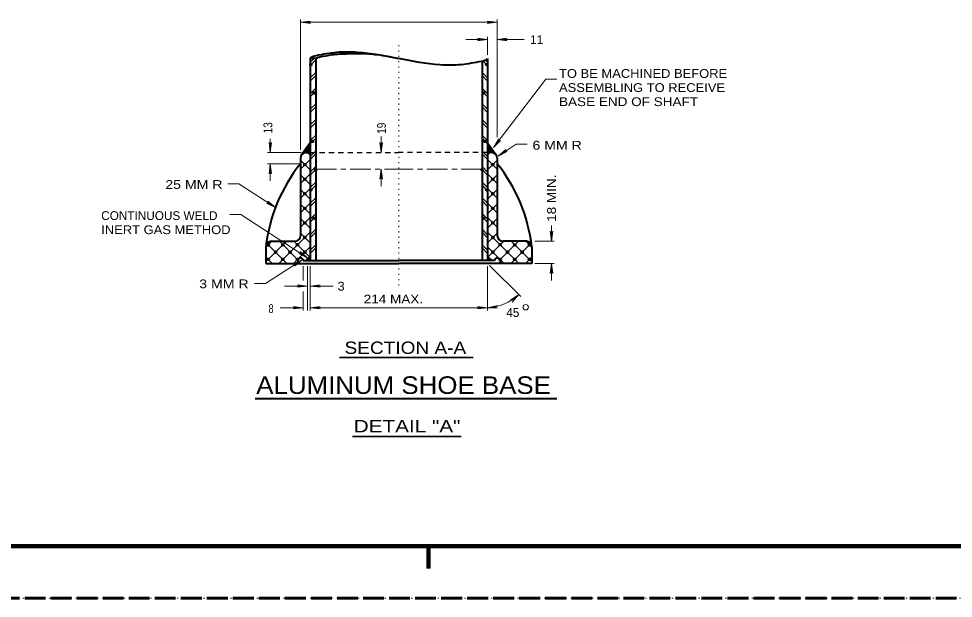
# Model space of a CAD drawing. Extents: x 312583 to 312854, y 144419 to 144597.
# Drawn here: x 312691.9 to 312772.7, y 144418.6 to 144468.7 of the extents above; entities that cross this region are included whole.
import ezdxf
from ezdxf.enums import TextEntityAlignment as Align

# ---------------------------------------------------------------- set-up
doc = ezdxf.new("R2010")
doc.units = 0
doc.header["$LTSCALE"] = 0.3
doc.header["$PDMODE"] = 32
doc.header["$PDSIZE"] = 0.15
for name, pattern in [('DOTTED', [1.5, 0.3, -1.2]), ('LONG_DASH_SHORT_DASH', [9.9, 6, -1.2, 1.5, -1.2]), ('LONG_DASHED', [7.5, 6, -1.5]), ('SHORT_DASHED', [2.7, 1.5, -1.2])]:
    doc.linetypes.add(name, pattern=pattern)
for name, color, linetype, lineweight in [('1', 7, 'Continuous', 40), ('2', 7, 'Continuous', 13), ('62', 7, 'DOTTED', 13), ('63', 7, 'LONG_DASHED', 60)]:
    doc.layers.add(name, color=color, linetype=linetype, lineweight=lineweight)

msp = doc.modelspace()

# ---------------------------------------------------------------- linework, layer by layer
at = {"layer": '1'}
for p, q in [((312717.1224, 144465.2785), (312717.1224, 144447.7909)), ((312717.6054, 144465.2785), (312717.1224, 144465.2785)), ((312717.6054, 144465.2785), (312717.6054, 144447.7909)), ((312732.4557, 144465.2785), (312732.4557, 144447.7909)), ((312731.9804, 144465.0332), (312731.9804, 144447.7909)), ((312717.1224, 144457.9722), (312716.3787, 144456.9372)), ((312732.4557, 144457.9722), (312733.2071, 144456.9372)), ((312716.2867, 144456.6535), (312716.2867, 144449.9452)), ((312716.7697, 144457.1365), (312717.1301, 144457.1365)), ((312732.8161, 144457.1365), (312732.4557, 144457.1365)), ((312733.2991, 144456.6535), (312733.2991, 144449.9452)), ((312713.7721, 144449.4699), (312715.8114, 144449.4699)), ((312735.8137, 144449.4699), (312733.7744, 144449.4699)), ((312713.2891, 144448.9869), (312713.2891, 144447.5532)), ((312736.2891, 144448.9869), (312736.2891, 144447.5532)), ((312713.2891, 144447.5532), (312724.7891, 144447.5532)), ((312716.0491, 144447.7909), (312716.0491, 144447.5532)), ((312716.5244, 144447.7909), (312724.7891, 144447.7909)), ((312716.7544, 144447.7909), (312717.1224, 144448.1589)), ((312733.0537, 144447.7909), (312724.7891, 144447.7909)), ((312736.2891, 144447.5532), (312724.7891, 144447.5532)), ((312732.8314, 144447.7909), (312732.4557, 144448.1589)), ((312733.5367, 144447.7909), (312733.5367, 144447.5532))]:
    msp.add_line(p, q, dxfattribs=at)
at = {"layer": '1', "lineweight": 13}
for p, q in [((312717.1224, 144464.9489), (312717.4597, 144465.2785)), ((312717.1224, 144464.6805), (312717.6054, 144465.1559)), ((312732.4557, 144464.6805), (312732.0877, 144465.0485)), ((312732.4557, 144464.9489), (312732.2564, 144465.1482)), ((312717.1224, 144463.5919), (312717.6054, 144464.0749)), ((312717.1224, 144463.3235), (312717.6054, 144463.7989)), ((312732.4557, 144463.5919), (312731.9804, 144464.0749)), ((312732.4557, 144463.3235), (312731.9804, 144463.7989)), ((312717.1224, 144462.2349), (312717.6054, 144462.7179)), ((312717.1224, 144461.9665), (312717.6054, 144462.4495)), ((312732.4557, 144462.2349), (312731.9804, 144462.7179)), ((312732.4557, 144461.9665), (312731.9804, 144462.4495)), ((312717.1224, 144460.8855), (312717.6054, 144461.3609)), ((312732.4557, 144460.8855), (312731.9804, 144461.3609)), ((312717.1224, 144460.6095), (312717.6054, 144461.0925)), ((312732.4557, 144460.6095), (312731.9804, 144461.0925)), ((312717.1224, 144459.5285), (312717.6054, 144460.0039)), ((312717.1224, 144459.2525), (312717.6054, 144459.7355)), ((312732.4557, 144459.5285), (312731.9804, 144460.0039)), ((312732.4557, 144459.2525), (312731.9804, 144459.7355)), ((312717.1224, 144458.1715), (312717.6054, 144458.6545)), ((312717.1224, 144457.8955), (312717.6054, 144458.3785)), ((312732.4557, 144458.1715), (312731.9804, 144458.6545)), ((312732.4634, 144457.8955), (312731.9804, 144458.3785)), ((312717.1224, 144456.8145), (312717.6054, 144457.2975)), ((312732.4557, 144456.8145), (312731.9804, 144457.2975)), ((312716.2867, 144455.7182), (312717.1301, 144456.5539)), ((312717.1301, 144455.6415), (312716.2867, 144456.4849)), ((312717.1301, 144456.9065), (312716.9001, 144457.1365)), ((312717.1224, 144456.5462), (312717.6054, 144457.0215)), ((312732.4557, 144456.5462), (312731.9804, 144457.0215)), ((312732.4557, 144456.9065), (312732.6857, 144457.1365)), ((312733.2991, 144455.7182), (312732.4557, 144456.5539)), ((312732.4557, 144455.6415), (312733.2991, 144456.4849)), ((312717.1224, 144455.4575), (312717.6054, 144455.9405)), ((312717.1224, 144455.1892), (312717.6054, 144455.6722)), ((312732.4557, 144455.4575), (312731.9804, 144455.9405)), ((312732.4557, 144455.1892), (312731.9804, 144455.6722)), ((312716.2867, 144454.4609), (312717.1301, 144455.2965)), ((312717.1301, 144454.3765), (312716.2867, 144455.2199)), ((312733.2991, 144454.4609), (312732.4557, 144455.2965)), ((312732.4557, 144454.3765), (312733.2991, 144455.2199)), ((312716.2867, 144453.1959), (312717.1301, 144454.0392)), ((312717.1224, 144454.1082), (312717.6054, 144454.5835)), ((312717.1224, 144453.8322), (312717.6054, 144454.3152)), ((312732.4557, 144454.1082), (312731.9804, 144454.5835)), ((312732.4557, 144453.8322), (312731.9804, 144454.3152)), ((312733.2991, 144453.1959), (312732.4557, 144454.0392)), ((312717.1301, 144453.1192), (312716.2867, 144453.9549)), ((312717.1301, 144452.7512), (312717.6054, 144453.2265)), ((312732.4557, 144452.7512), (312731.9804, 144453.2265)), ((312732.4557, 144453.1192), (312733.2991, 144453.9549)), ((312716.2867, 144451.9385), (312717.1301, 144452.7742)), ((312717.1224, 144451.8542), (312716.2867, 144452.6899)), ((312717.1224, 144452.4829), (312717.6054, 144452.9582)), ((312732.4557, 144452.4829), (312731.9804, 144452.9582)), ((312733.2991, 144451.9385), (312732.4557, 144452.7742)), ((312732.4557, 144451.8542), (312733.2991, 144452.6899)), ((312717.1224, 144451.3942), (312717.6054, 144451.8772)), ((312717.1224, 144451.1259), (312717.6054, 144451.6012)), ((312732.4557, 144451.3942), (312731.9804, 144451.8772)), ((312732.4557, 144451.1259), (312731.9804, 144451.6012)), ((312716.2867, 144450.6735), (312717.1224, 144451.5169)), ((312717.1224, 144450.5892), (312716.2867, 144451.4325)), ((312733.2991, 144450.6735), (312732.4557, 144451.5169)), ((312732.4557, 144450.5892), (312733.2991, 144451.4325)), ((312714.4237, 144447.5532), (312717.1301, 144450.2519)), ((312717.1224, 144449.3319), (312716.2867, 144450.1675)), ((312717.1224, 144450.0372), (312717.6054, 144450.5202)), ((312717.1224, 144449.7689), (312717.6054, 144450.2519)), ((312732.4557, 144450.0372), (312731.9804, 144450.5202)), ((312732.4557, 144449.7689), (312731.9804, 144450.2519)), ((312735.1621, 144447.5532), (312732.4557, 144450.2519)), ((312732.4557, 144449.3319), (312733.2991, 144450.1675)), ((312713.2891, 144447.6835), (312715.0754, 144449.4699)), ((312713.2891, 144448.9409), (312713.8181, 144449.4699)), ((312715.1137, 144447.5532), (312713.2891, 144449.3702)), ((312716.0644, 144447.8675), (312714.4621, 144449.4699)), ((312717.1224, 144448.0669), (312715.7271, 144449.4699)), ((312717.1224, 144448.6879), (312717.6054, 144449.1632)), ((312732.4557, 144448.6879), (312731.9804, 144449.1632)), ((312732.4557, 144448.0669), (312733.8587, 144449.4699)), ((312733.5214, 144447.8675), (312735.1237, 144449.4699)), ((312734.4721, 144447.5532), (312736.2891, 144449.3702)), ((312736.2891, 144447.6835), (312734.5027, 144449.4699)), ((312736.2891, 144448.9409), (312735.7677, 144449.4699)), ((312715.6811, 144447.5532), (312717.1301, 144448.9945)), ((312717.1224, 144448.4119), (312717.6054, 144448.8949)), ((312732.4557, 144448.4119), (312731.9804, 144448.8949)), ((312733.8971, 144447.5532), (312732.4557, 144448.9945)), ((312713.8487, 144447.5532), (312713.2891, 144448.1129)), ((312717.5901, 144447.7909), (312717.6054, 144447.8062)), ((312731.9957, 144447.7909), (312731.9804, 144447.8062)), ((312735.7371, 144447.5532), (312736.2891, 144448.1129))]:
    msp.add_line(p, q, dxfattribs=at)
at = {"layer": '1', "lineweight": 25}
for p, q in [((312716.5014, 144457.1135), (312717.1224, 144457.7345)), ((312716.6087, 144457.1212), (312717.1224, 144457.6349)), ((312716.7084, 144457.1289), (312717.1224, 144457.5429)), ((312716.7467, 144457.4509), (312717.1224, 144457.8265)), ((312716.8157, 144457.1365), (312717.1224, 144457.4509)), ((312716.9077, 144457.1365), (312717.1224, 144457.3512)), ((312716.9921, 144457.7882), (312717.1224, 144457.9262)), ((312716.9997, 144457.1365), (312717.1224, 144457.2592)), ((312732.5937, 144457.7882), (312732.4557, 144457.9262)), ((312732.8314, 144457.4509), (312732.4557, 144457.8265)), ((312733.0767, 144457.1135), (312732.4557, 144457.7345)), ((312732.9771, 144457.1212), (312732.4557, 144457.6349)), ((312732.8697, 144457.1289), (312732.4557, 144457.5429)), ((312732.7701, 144457.1365), (312732.4557, 144457.4509)), ((312732.6781, 144457.1365), (312732.4557, 144457.3512)), ((312732.5784, 144457.1365), (312732.4557, 144457.2592)), ((312717.0994, 144457.1365), (312717.1224, 144457.1672)), ((312732.4864, 144457.1365), (312732.4557, 144457.1672)), ((312716.8387, 144447.7909), (312717.1224, 144448.0822)), ((312716.9307, 144447.7909), (312717.1224, 144447.9825)), ((312717.0304, 144447.7909), (312717.1224, 144447.8905)), ((312717.1224, 144447.7909), (312717.1224, 144447.7985)), ((312732.7471, 144447.7909), (312732.4557, 144448.0822)), ((312732.6551, 144447.7909), (312732.4557, 144447.9825)), ((312732.5554, 144447.7909), (312732.4557, 144447.8905)), ((312732.4634, 144447.7909), (312732.4557, 144447.7985))]:
    msp.add_line(p, q, dxfattribs=at)
at = {"layer": '1', "linetype": 'SHORT_DASHED', "lineweight": 25}
for p in [(312717.1301, 144457.1365), (312732.4557, 144457.1365)]:
    msp.add_line(p, (312724.7891, 144457.1365), dxfattribs=at)
at = {"layer": '1', "linetype": 'LONG_DASH_SHORT_DASH', "lineweight": 13}
for p in [(312717.6054, 144455.6952), (312731.9804, 144455.6952)]:
    msp.add_line(p, (312724.7891, 144455.6952), dxfattribs=at)
at = {"layer": '1', "lineweight": 158}
for p, q in [((312616.5, 144423.0846), (312849, 144423.0846)), ((312727.35, 144421.1646), (312727.35, 144423.0846))]:
    msp.add_line(p, q, dxfattribs=at)
at = {"layer": '1'}
for centre, radius, start, end in [((312716.7659, 144456.6555), 0.4792, 90, 180), ((312732.8161, 144456.6555), 0.4792, 0, 90), ((312727.4036, 144447.3247), 14.2103, 141.47211, 173.27514), ((312722.1784, 144447.3247), 14.2103, 6.72486, 38.52789), ((312715.8076, 144449.9471), 0.4792, 270, 0), ((312733.7744, 144449.9471), 0.4792, 180, 270), ((312713.7701, 144448.9888), 0.4792, 90, 180), ((312735.8118, 144448.9888), 0.4792, 0, 90), ((312716.2867, 144447.7909), 0.2396, 0, 180), ((312733.2952, 144447.7909), 0.2396, 0, 180)]:
    msp.add_arc(centre, radius, start, end, dxfattribs=at)
for points in [[(312717.1224, 144465.2785), (312717.2221, 144465.3782), (312717.6514, 144465.5392), (312719.4071, 144465.8229), (312721.2241, 144465.8382), (312724.7891, 144465.2785)], [(312717.6054, 144465.2785), (312717.6974, 144465.3399), (312717.9734, 144465.4165), (312719.0237, 144465.6159), (312719.6907, 144465.6695), (312721.1167, 144465.7155), (312722.1824, 144465.6849), (312722.9031, 144465.6159), (312724.7891, 144465.2785)], [(312732.4557, 144465.2785), (312732.3637, 144465.1865), (312731.9267, 144465.0255), (312730.1787, 144464.7419), (312728.3617, 144464.7265), (312724.7891, 144465.2785)]]:
    msp.add_spline(points, degree=3, dxfattribs=at)
for p in [(312717.1914, 144464.7495), (312732.3867, 144464.7495), (312717.4674, 144462.3039), (312732.1184, 144462.3039), (312717.3294, 144458.1025), (312732.2564, 144458.1025), (312716.6701, 144456.1015), (312717.5977, 144455.6645), (312731.9804, 144455.6645), (312732.9157, 144456.1015), (312716.6701, 144454.8365), (312732.9157, 144454.8365), (312717.1914, 144453.9012), (312732.3867, 144453.9012), (312716.6701, 144453.5792), (312732.9157, 144453.5792), (312716.6624, 144452.3142), (312732.9157, 144452.3142), (312717.4674, 144451.4632), (312732.1184, 144451.4632), (312716.6624, 144451.0569), (312732.9234, 144451.0569), (312713.5114, 144449.1555), (312714.7687, 144449.1555), (312716.0337, 144449.1632), (312716.6624, 144449.7919), (312732.9234, 144449.7919), (312733.5521, 144449.1632), (312734.8171, 144449.1555), (312736.0744, 144449.1555), (312714.1401, 144448.5269), (312715.3974, 144448.5269), (312716.6624, 144448.5269), (312732.9234, 144448.5269), (312734.1807, 144448.5269), (312735.4457, 144448.5269), (312713.5037, 144447.8982), (312714.7687, 144447.8982), (312716.0337, 144447.8982), (312733.5521, 144447.8982), (312734.8171, 144447.8982), (312736.0744, 144447.8982)]:
    msp.add_point(p, dxfattribs=at)
at = {"layer": '2'}
for p, q in [((312716.2867, 144457.3742), (312716.2867, 144468.6442)), ((312716.2867, 144468.4065), (312717.1531, 144468.5139)), ((312717.1531, 144468.5139), (312716.8771, 144468.4065)), ((312732.4327, 144468.5139), (312732.7087, 144468.4065)), ((312733.2991, 144468.4065), (312732.4327, 144468.5139)), ((312733.2991, 144458.4782), (312733.2991, 144468.6442)), ((312716.2867, 144468.4065), (312733.2991, 144468.4065)), ((312716.2867, 144468.4065), (312717.1531, 144468.2992)), ((312717.1531, 144468.2992), (312716.8771, 144468.4065)), ((312732.4327, 144468.2992), (312732.7087, 144468.4065)), ((312733.2991, 144468.4065), (312732.4327, 144468.2992)), ((312732.4557, 144466.9192), (312730.5927, 144466.9192)), ((312731.5894, 144467.0265), (312731.8654, 144466.9192)), ((312732.4557, 144466.9192), (312731.5894, 144467.0265)), ((312731.5894, 144466.8119), (312731.8654, 144466.9192)), ((312732.4557, 144466.9192), (312731.5894, 144466.8119)), ((312732.4557, 144465.6005), (312732.4557, 144467.1569)), ((312733.2991, 144466.9192), (312734.1654, 144467.0265)), ((312733.2991, 144466.9192), (312735.6297, 144466.9192)), ((312733.2991, 144466.9192), (312734.1654, 144466.8119)), ((312734.1654, 144467.0265), (312733.8894, 144466.9192)), ((312734.1654, 144466.8119), (312733.8894, 144466.9192)), ((312737.4927, 144463.4999), (312732.9771, 144457.5735)), ((312737.4927, 144463.4999), (312738.4511, 144463.4999)), ((312713.5727, 144458.0029), (312713.6801, 144457.7269)), ((312713.6801, 144457.1365), (312713.5727, 144458.0029)), ((312713.6801, 144457.1365), (312713.6801, 144458.3427)), ((312713.7874, 144458.0029), (312713.6801, 144457.7269)), ((312713.6801, 144457.1365), (312713.7874, 144458.0029)), ((312723.1561, 144458.0029), (312723.2634, 144457.7269)), ((312723.2634, 144457.1365), (312723.1561, 144458.0029)), ((312723.2634, 144457.1365), (312723.2634, 144458.5165)), ((312723.3707, 144458.0029), (312723.2634, 144457.7269)), ((312723.2634, 144457.1365), (312723.3707, 144458.0029)), ((312732.9771, 144457.5735), (312733.4141, 144458.3249)), ((312732.9771, 144457.5735), (312733.5904, 144458.1945)), ((312733.4141, 144458.3249), (312733.3374, 144458.0412)), ((312733.5904, 144458.1945), (312733.3374, 144458.0412)), ((312733.3757, 144456.8299), (312734.0351, 144457.4049)), ((312733.3757, 144456.8299), (312734.1577, 144457.2285)), ((312734.0351, 144457.4049), (312733.8664, 144457.1595)), ((312734.1577, 144457.2285), (312733.8664, 144457.1595)), ((312716.3481, 144457.1365), (312713.4424, 144457.1365)), ((312716.3481, 144456.1782), (312713.4424, 144456.1782)), ((312713.6801, 144456.1782), (312713.5727, 144455.3119)), ((312713.5727, 144455.3119), (312713.6801, 144455.5879)), ((312713.6801, 144454.6985), (312713.6801, 144456.1782)), ((312713.6801, 144456.1782), (312713.7874, 144455.3119)), ((312713.7874, 144455.3119), (312713.6801, 144455.5879)), ((312723.2634, 144455.6952), (312723.1561, 144454.8289)), ((312723.2634, 144454.2232), (312723.2634, 144455.6952)), ((312723.2634, 144455.6952), (312723.3707, 144454.8289)), ((312723.1561, 144454.8289), (312723.2634, 144455.1049)), ((312723.3707, 144454.8289), (312723.2634, 144455.1049)), ((312710.0077, 144454.4225), (312710.9661, 144454.4225)), ((312714.1324, 144452.3755), (312710.9661, 144454.4225)), ((312713.3427, 144452.7589), (312713.6341, 144452.6975)), ((312714.1324, 144452.3755), (312713.3427, 144452.7589)), ((312713.4577, 144452.9352), (312713.6341, 144452.6975)), ((312714.1324, 144452.3755), (312713.4577, 144452.9352)), ((312710.1841, 144451.7699), (312711.1424, 144451.7699)), ((312716.9307, 144448.0132), (312711.1424, 144451.7699)), ((312737.9834, 144449.4699), (312737.9834, 144450.8256)), ((312737.8761, 144450.3362), (312737.9834, 144450.0602)), ((312737.9834, 144449.4699), (312737.8761, 144450.3362)), ((312738.0907, 144450.3362), (312737.9834, 144450.0602)), ((312737.9834, 144449.4699), (312738.0907, 144450.3362)), ((312736.5344, 144449.4699), (312738.2211, 144449.4699)), ((312716.1411, 144448.3965), (312716.4324, 144448.3352)), ((312716.9307, 144448.0132), (312716.1411, 144448.3965)), ((312716.2561, 144448.5805), (312716.4324, 144448.3352)), ((312716.9307, 144448.0132), (312716.2561, 144448.5805)), ((312716.4401, 144447.8675), (312713.2737, 144445.8205)), ((312716.4401, 144447.8675), (312715.6504, 144447.4919)), ((312715.6504, 144447.4919), (312715.9417, 144447.5455)), ((312716.4401, 144447.8675), (312715.7654, 144447.3079)), ((312715.7654, 144447.3079), (312715.9417, 144447.5455)), ((312736.5344, 144447.5532), (312738.2211, 144447.5532)), ((312737.9834, 144447.5532), (312737.8761, 144446.6869)), ((312737.9834, 144446.0735), (312737.9834, 144447.5532)), ((312737.9834, 144447.5532), (312738.0907, 144446.6869)), ((312716.5244, 144447.3155), (312716.5244, 144446.0735)), ((312716.8847, 144447.3155), (312716.8847, 144443.4822)), ((312717.1224, 144447.3155), (312717.1224, 144443.4822)), ((312732.4557, 144447.3155), (312732.4557, 144443.4822)), ((312732.6321, 144447.3845), (312735.3461, 144444.6782)), ((312737.8761, 144446.6869), (312737.9834, 144446.9629)), ((312738.0907, 144446.6869), (312737.9834, 144446.9629)), ((312712.3154, 144445.8205), (312713.2737, 144445.8205)), ((312716.8847, 144445.5982), (312714.8991, 144445.5982)), ((312716.0184, 144445.7055), (312716.2944, 144445.5982)), ((312716.8847, 144445.5982), (312716.0184, 144445.7055)), ((312716.0184, 144445.4909), (312716.2944, 144445.5982)), ((312716.8847, 144445.5982), (312716.0184, 144445.4909)), ((312716.5244, 144445.1152), (312716.5244, 144443.4822)), ((312717.1224, 144445.5982), (312717.9887, 144445.7055)), ((312719.1157, 144445.5982), (312717.1224, 144445.5982)), ((312717.1224, 144445.5982), (312717.9887, 144445.4909)), ((312717.9887, 144445.7055), (312717.7127, 144445.5982)), ((312717.9887, 144445.4909), (312717.7127, 144445.5982)), ((312735.1621, 144444.8545), (312734.4337, 144444.3715)), ((312734.4337, 144444.3715), (312734.7174, 144444.4712)), ((312735.1621, 144444.8545), (312734.5717, 144444.2105)), ((312734.5717, 144444.2105), (312734.7174, 144444.4712)), ((312716.5244, 144443.7199), (312714.5387, 144443.7199)), ((312715.6581, 144443.8272), (312715.9341, 144443.7199)), ((312716.5244, 144443.7199), (312715.6581, 144443.8272)), ((312715.6581, 144443.6125), (312715.9341, 144443.7199)), ((312716.5244, 144443.7199), (312715.6581, 144443.6125)), ((312717.1224, 144443.7199), (312717.9887, 144443.8272)), ((312717.1224, 144443.7199), (312732.4557, 144443.7199)), ((312717.1224, 144443.7199), (312717.9887, 144443.6125)), ((312717.9887, 144443.8272), (312717.7127, 144443.7199)), ((312717.9887, 144443.6125), (312717.7127, 144443.7199)), ((312731.5894, 144443.8272), (312731.8654, 144443.7199)), ((312732.4557, 144443.7199), (312731.5894, 144443.8272)), ((312731.5894, 144443.6125), (312731.8654, 144443.7199)), ((312732.4557, 144443.7199), (312731.5894, 144443.6125)), ((312732.4557, 144443.7199), (312733.3144, 144443.9115)), ((312732.4557, 144443.7199), (312733.3297, 144443.6969)), ((312733.3144, 144443.9115), (312733.0461, 144443.7735)), ((312733.3297, 144443.6969), (312733.0461, 144443.7735))]:
    msp.add_line(p, q, dxfattribs=at)
at = {"layer": '2', "linetype": 'DOTTED'}
msp.add_line((312724.7891, 144445.6365), (312724.7891, 144466.5972), dxfattribs=at)
at = {"layer": '2', "lineweight": 35}
for p, q in [((312719.6732, 144439.4142), (312731.2164, 144439.4142)), ((312720.777, 144432.5879), (312730.1655, 144432.5879))]:
    msp.add_line(p, q, dxfattribs=at)
at = {"layer": '2', "lineweight": 40}
msp.add_line((312712.3849, 144435.8692), (312738.4484, 144435.8692), dxfattribs=at)
at = {"layer": '2'}
msp.add_lwpolyline([(312733.3757, 144456.8299), (312734.9321, 144457.8802), (312735.8904, 144457.8802)], dxfattribs=at)
msp.add_circle((312735.7582, 144443.7659), 0.2351, dxfattribs=at)
msp.add_arc((312732.2777, 144447.9218), 4.2077, 272.45055, 313.23855, dxfattribs=at)
at = {"layer": '62'}
msp.add_lwpolyline([(312601.2, 144418.5846), (312853.5, 144418.5846), (312853.5, 144596.7846)], dxfattribs=at)
at = {"layer": '63'}
msp.add_line((312851.75, 144418.5846), (312583.526, 144418.5846), dxfattribs=at)

# ---------------------------------------------------------------- texts
at = {"layer": '2'}
for s, p in [('11 ', (312736.1412, 144466.5265)), ('CONTINUOUS WELD', (312699.0658, 144451.3066)), ('45', (312734.0793, 144442.9221))]:
    msp.add_text(s, height=0.76, dxfattribs=at).set_placement(p)
for s, width, p in [('TO BE MACHINED BEFORE', 1.1, (312738.6369, 144463.6005)), ('ASSEMBLING TO RECEIVE', 1.1, (312738.6369, 144462.3805)), ('BASE END OF SHAFT', 1.15, (312738.6369, 144461.1605)), ('6 MM R', 1.2, (312736.3379, 144457.3932)), ('25 MM R', 1.2, (312704.6041, 144453.9969)), ('INERT GAS METHOD', 1.1, (312699.0658, 144450.0866)), ('3 MM R', 1.2, (312707.5381, 144445.4025)), ('3 ', 1.1, (312719.4872, 144445.1997)), ('214 MAX.', 1.15, (312721.7547, 144444.0897)), ('8', 0.75, (312713.5295, 144443.2613))]:
    msp.add_text(s, height=0.76, dxfattribs=dict(at, width=width)).set_placement(p)
for s, width, p in [('13', 0.85, (312713.8524, 144458.798)), ('19', 0.85, (312723.6676, 144458.7626)), ('18 MIN.', 1.15, (312738.3685, 144451.1465))]:
    msp.add_text(s, height=0.76, rotation=90, dxfattribs=dict(at, width=width)).set_placement(p)
for s, height, width, p in [('SECTION A-A', 1.07, 1.15, (312725.353, 144439.7229)), ('ALUMINUM SHOE BASE', 1.52, 1.1, (312725.1996, 144436.264)), ('DETAIL "A"', 1.07, 1.25, (312725.5045, 144432.9414))]:
    msp.add_text(s, height=height, dxfattribs=dict(at, width=width)).set_placement(p, align=Align.CENTER)

doc.saveas('drawing.dxf')
